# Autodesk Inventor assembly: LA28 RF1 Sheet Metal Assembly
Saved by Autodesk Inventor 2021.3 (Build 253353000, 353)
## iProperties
Created: 2023-01
Part Number: LA28 RF1 Sheet Metal Assembly
Document SubType Name: Assembly
Designer: AdminForWorker
Title: LA28 RF1 Sheet Metal Assembly v3
Author: AdminForWorker
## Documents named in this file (8)
- c:\worker\convert-fusion-r08-cosv3\tmp\job-1\7\output\files\be2e730f-f331-4d02-b9c8-0db6989d2b3d\LA28 RF1 Sheet Metal Assembly v3.iam
- c:\worker\convert-fusion-r08-cosv3\tmp\job-1\7\output\files\be2e730f-f331-4d02-b9c8-0db6989d2b3d\LA28RF1 Front Rear C Channel^la28RF1 SHEET METAL ASSEMBLY.ipt
- c:\worker\convert-fusion-r08-cosv3\tmp\job-1\7\output\files\be2e730f-f331-4d02-b9c8-0db6989d2b3d\LA28RF1 Center Bar^la28RF1 SHEET METAL ASSEMBLY.ipt
- c:\worker\convert-fusion-r08-cosv3\tmp\job-1\7\output\files\be2e730f-f331-4d02-b9c8-0db6989d2b3d\AL28RF1 Outer Bar^la28RF1 SHEET METAL ASSEMBLY.ipt
- c:\worker\convert-fusion-r08-cosv3\tmp\job-1\7\output\files\be2e730f-f331-4d02-b9c8-0db6989d2b3d\Inclinometer Mount Plate^la28RF1 SHEET METAL ASSEMBLY.ipt
- c:\worker\convert-fusion-r08-cosv3\tmp\job-1\7\output\files\be2e730f-f331-4d02-b9c8-0db6989d2b3d\Stabilizing Tube^la28RF1 SHEET METAL ASSEMBLY.ipt
- c:\worker\convert-fusion-r08-cosv3\tmp\job-1\7\output\files\be2e730f-f331-4d02-b9c8-0db6989d2b3d\Rear Connection Arm^la28RF1 SHEET METAL ASSEMBLY.ipt
- c:\worker\convert-fusion-r08-cosv3\tmp\job-1\7\output\files\be2e730f-f331-4d02-b9c8-0db6989d2b3d\LA18 LA28 Front Connection Tongue^la28RF1 SHEET METAL ASSEMBLY.ipt
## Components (15 placed, 7 different names)
1. LA28RF1 Front Rear C Channel^la28RF1 SHEET METAL ASSEMBLY:1
2. LA28RF1 Front Rear C Channel^la28RF1 SHEET METAL ASSEMBLY:2
3. LA28RF1 Center Bar^la28RF1 SHEET METAL ASSEMBLY:1
4. LA28RF1 Center Bar^la28RF1 SHEET METAL ASSEMBLY:2
5. AL28RF1 Outer Bar^la28RF1 SHEET METAL ASSEMBLY:1
6. AL28RF1 Outer Bar^la28RF1 SHEET METAL ASSEMBLY:2
7. AL28RF1 Outer Bar^la28RF1 SHEET METAL ASSEMBLY:3
8. AL28RF1 Outer Bar^la28RF1 SHEET METAL ASSEMBLY:4
9. Inclinometer Mount Plate^la28RF1 SHEET METAL ASSEMBLY:1
10. Stabilizing Tube^la28RF1 SHEET METAL ASSEMBLY:1
11. Stabilizing Tube^la28RF1 SHEET METAL ASSEMBLY:2
12. Rear Connection Arm^la28RF1 SHEET METAL ASSEMBLY:1
13. Rear Connection Arm^la28RF1 SHEET METAL ASSEMBLY:2
14. LA18 LA28 Front Connection Tongue^la28RF1 SHEET METAL ASSEMBLY:1
15. LA18 LA28 Front Connection Tongue^la28RF1 SHEET METAL ASSEMBLY:2
